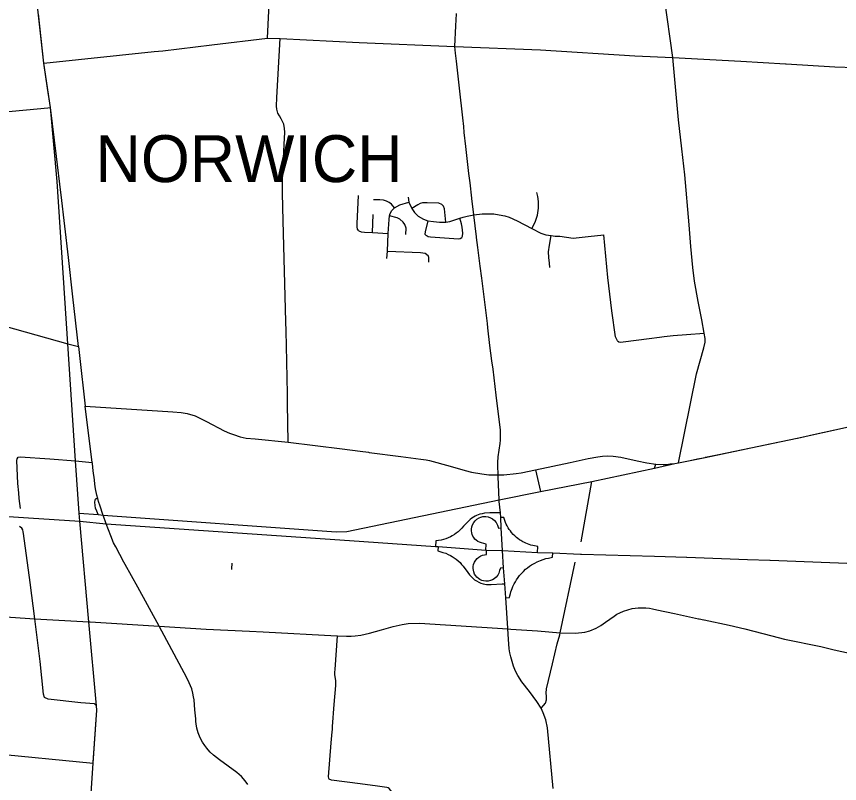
# Model space of a CAD drawing. Extents: x 1755200 to 1902939, y 644115 to 788070.
# Drawn here: x 1776912 to 1792682, y 716346 to 731049 of the extents above; entities that cross this region are included whole.
import ezdxf

# ---------------------------------------------------------------- set-up
doc = ezdxf.new("R2010")
doc.units = 0
for name, color, linetype in [('GM_X_City_Street', 7, 'Continuous'), ('GM_X_County_Road', 7, 'Continuous'), ('GM_X_Interchange_Ramps', 7, 'Continuous'), ('GM_X_Interstate_Route', 7, 'Continuous'), ('GM_X_Township', 7, 'Continuous'), ('GM_X_Township_Road', 7, 'Continuous'), ('GM_X_Township_Text', 7, 'Continuous')]:
    doc.layers.add(name, color=color, linetype=linetype)

msp = doc.modelspace()

# ---------------------------------------------------------------- linework, layer by layer
at = {"layer": 'GM_X_City_Street'}
for points in [[(1781722, 730635), (1781759, 731426)], [(1789599, 722496), (1789944, 724200), (1790081, 724699), (1790105, 724804), (1790108, 724874), (1790088, 724979), (1790041, 725234), (1789973, 725588), (1789906, 725972), (1789873, 726237), (1789834, 726638), (1789800, 727052), (1789717, 728011), (1789660, 728513), (1789596, 729067), (1789486, 730260), (1789329, 731408)], [(1777437, 730152), (1777333, 731099)], [(1785481, 728938), (1785462, 729108), (1785399, 729675), (1785340, 730193), (1785323, 730344), (1785311, 730474), (1785329, 730870), (1785343, 731097), (1785344, 731105)], [(1780654, 730505), (1781722, 730635), (1781962, 730623), (1783476, 730548), (1785311, 730474)], [(1782072, 725200), (1782025, 727132), (1782011, 727662), (1782011, 727904), (1782016, 728049), (1782039, 728595), (1782052, 728830), (1782048, 728903), (1782034, 728984), (1782010, 729034), (1781982, 729089), (1781950, 729141), (1781921, 729194), (1781903, 729270), (1781893, 729331), (1781902, 729493), (1781962, 730623)], [(1777437, 730152), (1779548, 730374)], [(1785311, 730474), (1786954, 730410), (1788762, 730295), (1789486, 730260), (1790791, 730191), (1791647, 730138), (1791657, 730138)], [(1777509, 729675), (1777437, 730152)], [(1791657, 730138), (1792592, 730086), (1793371, 730056), (1793934, 730030)], [(1785638, 727562), (1785638, 727565), (1785602, 727860), (1785582, 728036), (1785520, 728559), (1785493, 728824), (1785481, 728938)], [(1786787, 726983), (1786850, 727104), (1786896, 727243), (1786916, 727371), (1786915, 727505), (1786903, 727598), (1786882, 727676)], [(1783473, 726942), (1783447, 726974), (1783438, 727018), (1783442, 727081), (1783466, 727619)], [(1784156, 727383), (1784098, 727453), (1784050, 727485), (1784005, 727508), (1783944, 727527), (1783871, 727531), (1783814, 727533), (1783752, 727532)], [(1784417, 727588), (1784432, 727489), (1784485, 727367), (1784541, 727288), (1784607, 727223), (1784713, 727163), (1784793, 727134), (1784905, 727116), (1785020, 727109), (1785137, 727107), (1785214, 727119), (1785274, 727137), (1785407, 727185), (1785469, 727203), (1785548, 727223), (1785678, 727244), (1785835, 727263), (1785929, 727266), (1786058, 727263), (1786160, 727248), (1786268, 727226), (1786355, 727200), (1786505, 727130), (1786787, 726983), (1786961, 726898), (1787055, 726866), (1787155, 726848), (1787236, 726835), (1787325, 726835), (1787577, 726802), (1787866, 726833), (1788164, 726860)], [(1785725, 726822), (1785678, 727244), (1785638, 727562)], [(1784011, 726412), (1784018, 726553), (1784035, 726887), (1784050, 727154), (1784058, 727227), (1784073, 727275), (1784101, 727327), (1784156, 727383), (1784256, 727440), (1784432, 727489)], [(1785137, 727107), (1785111, 727360), (1785093, 727412), (1785059, 727447), (1785003, 727469), (1784778, 727479), (1784693, 727476), (1784650, 727464), (1784600, 727438), (1784485, 727367)], [(1783731, 726909), (1783748, 727253)], [(1784370, 726872), (1784377, 726993), (1784356, 727063), (1784319, 727107), (1784256, 727166), (1784209, 727188), (1784058, 727227)], [(1784793, 727134), (1784740, 726920), (1784739, 726876), (1784757, 726856), (1784779, 726841), (1784803, 726833), (1784842, 726826), (1785379, 726789), (1785416, 726794), (1785443, 726813), (1785461, 726837), (1785467, 726893), (1785451, 727009), (1785439, 727076), (1785407, 727185)], [(1783473, 726942), (1783516, 726918), (1783579, 726911), (1783731, 726909), (1784035, 726887)], [(1785944, 725080), (1785934, 725163), (1785829, 726034), (1785797, 726263), (1785749, 726618), (1785727, 726809), (1785725, 726822)], [(1787131, 726234), (1787123, 726318), (1787110, 726429), (1787108, 726536), (1787125, 726664), (1787155, 726848)], [(1788430, 724830), (1788414, 724854), (1788391, 724907), (1788322, 725405), (1788242, 726047), (1788164, 726860)], [(1784018, 726553), (1784656, 726527), (1784745, 726512), (1784800, 726470)], [(1784813, 726336), (1784815, 726427), (1784800, 726470)], [(1786023, 724447), (1785985, 724743), (1785944, 725080)], [(1788430, 724830), (1788453, 724811), (1788485, 724807), (1788535, 724810), (1789035, 724873), (1789230, 724902), (1789322, 724916), (1789493, 724935), (1789747, 724953), (1790088, 724979)], [(1786177, 722862), (1786186, 722926), (1786188, 722992), (1786185, 723126), (1786167, 723272), (1786100, 723790), (1786043, 724289), (1786023, 724447)], [(1782118, 722891), (1782108, 723626)], [(1792243, 723049), (1793294, 723280)], [(1791139, 722812), (1791871, 722968), (1791876, 722969)], [(1786144, 722227), (1786143, 722261), (1786134, 722441), (1786134, 722500), (1786139, 722606), (1786159, 722733), (1786177, 722862)], [(1790369, 722653), (1791139, 722812)], [(1783669, 722693), (1784274, 722615), (1784658, 722566), (1784761, 722550), (1784824, 722538), (1785222, 722427), (1785506, 722345), (1785630, 722316), (1785830, 722280), (1785960, 722266), (1786035, 722260), (1786143, 722261)], [(1786143, 722261), (1786248, 722260), (1786485, 722288), (1786583, 722303), (1786857, 722360), (1787188, 722430), (1787520, 722499), (1787864, 722574), (1788050, 722609), (1788142, 722622), (1788238, 722626), (1788343, 722621), (1788491, 722603), (1788802, 722533), (1788989, 722493), (1789163, 722468), (1789300, 722462), (1789367, 722464), (1789438, 722471), (1789524, 722482), (1789599, 722496)], [(1790113, 722599), (1790369, 722653)], [(1786857, 722360), (1786950, 721943), (1787934, 722138), (1789139, 722388), (1789163, 722468)], [(1789599, 722496), (1789790, 722531), (1789959, 722567)], [(1786163, 721749), (1786160, 721782), (1786144, 722227)], [(1787733, 720981), (1787934, 722138)], [(1786226, 720812), (1786201, 721246), (1786190, 721444), (1786184, 721537), (1786163, 721749)], [(1786327, 719326), (1786290, 719906), (1786268, 720174), (1786246, 720478), (1786226, 720812)], [(1787320, 719199), (1787329, 719236), (1787619, 720589)], [(1781038, 720449), (1781038, 720459), (1781044, 720567)], [(1786381, 719305), (1786895, 719271), (1787329, 719236), (1787624, 719226), (1787799, 719248), (1787899, 719274), (1788018, 719323), (1788109, 719374), (1788197, 719440), (1788282, 719499), (1788362, 719557), (1788417, 719590), (1788470, 719618), (1788546, 719649), (1788624, 719678), (1788707, 719700), (1788824, 719713), (1788924, 719715), (1788968, 719713), (1789040, 719705), (1789096, 719694), (1789183, 719676), (1789523, 719603), (1789981, 719504)], [(1790085, 719484), (1790089, 719483), (1790569, 719379), (1790869, 719309), (1791383, 719177), (1791627, 719116), (1792323, 718971), (1792577, 718912), (1792962, 718825)], [(1783263, 719169), (1783325, 719170), (1783403, 719178), (1783511, 719193), (1783677, 719231), (1783905, 719292), (1784132, 719358), (1784299, 719394), (1784417, 719415), (1784631, 719419), (1786328, 719309)], [(1786368, 718852), (1786355, 718926), (1786340, 719112), (1786328, 719309), (1786327, 719326)], [(1786328, 719309), (1786381, 719305)], [(1781637, 719255), (1783053, 719176)], [(1782968, 717441), (1782998, 717861), (1783028, 718226), (1783031, 718323), (1783015, 718429), (1783014, 718484), (1783018, 718530), (1783066, 719175)], [(1783053, 719176), (1783066, 719175), (1783237, 719168), (1783263, 719169)], [(1781345, 716326), (1781294, 716396), (1781222, 716481), (1781131, 716559), (1780799, 716801), (1780688, 716890), (1780624, 716945), (1780585, 716989), (1780557, 717023), (1780518, 717077), (1780476, 717141), (1780433, 717222), (1780393, 717317), (1780368, 717406), (1780353, 717490), (1780348, 717537), (1780346, 717584), (1780340, 717647)], [(1782943, 717125), (1782960, 717335)], [(1784287, 711268), (1784257, 712144), (1784154, 713990), (1784169, 714040), (1784177, 714106), (1784191, 714939), (1784196, 715048), (1784189, 715097), (1784160, 715152), (1784098, 715241), (1784082, 715270), (1784077, 715304), (1784083, 715438), (1784109, 715887), (1784118, 716104), (1784106, 716186), (1784052, 716249), (1784033, 716263), (1784011, 716269), (1783831, 716296), (1783496, 716342), (1782951, 716412), (1782905, 716430), (1782898, 716443)]]:
    msp.add_lwpolyline(points, dxfattribs=at)
at = {"layer": 'GM_X_County_Road'}
for points in [[(1779548, 730374), (1779718, 730392), (1780654, 730505)], [(1777565, 729305), (1777509, 729675)], [(1771794, 729168), (1772912, 729117), (1773134, 729105), (1773270, 729095), (1773412, 729078), (1773515, 729060), (1773633, 729037), (1773733, 729018), (1773839, 729000), (1773954, 728991), (1774076, 728987), (1774241, 728991), (1774436, 729008), (1777513, 729300)], [(1777513, 729300), (1777565, 729305)], [(1777761, 727673), (1777676, 728365), (1777565, 729305)], [(1778102, 724724), (1777991, 725673), (1777906, 726429), (1777766, 727631), (1777761, 727673)], [(1774090, 726031), (1775440, 725510), (1775595, 725449), (1775701, 725407), (1775843, 725352), (1777898, 724773), (1778050, 724736)], [(1782108, 723626), (1782105, 723813), (1782086, 724734), (1782077, 725019), (1782072, 725200)], [(1778050, 724736), (1778102, 724724)], [(1778102, 724724), (1778102, 724724), (1778122, 724551), (1778230, 723582)], [(1778230, 723582), (1779906, 723471), (1780068, 723459), (1780184, 723441), (1780336, 723397), (1780556, 723288), (1780893, 723105), (1780991, 723062), (1781071, 723035), (1781200, 722994), (1781312, 722967), (1781488, 722953), (1782118, 722891), (1783151, 722760), (1783499, 722716), (1783658, 722695), (1783669, 722693)], [(1778366, 722482), (1778364, 722500), (1778230, 723582)], [(1791876, 722969), (1792243, 723049)], [(1778567, 721503), (1778513, 721662), (1778485, 721753), (1778471, 721807), (1778452, 721875), (1778429, 721994), (1778416, 722082), (1778407, 722166), (1778383, 722339), (1778366, 722482)], [(1789959, 722567), (1790107, 722598), (1790113, 722599)], [(1778997, 720542), (1778970, 720591), (1778814, 720882), (1778774, 720958), (1778717, 721095), (1778630, 721327), (1778572, 721489), (1778567, 721503)], [(1780340, 717647), (1780330, 717759), (1780314, 717949), (1780306, 718007), (1780291, 718077), (1780271, 718161), (1780221, 718274), (1780174, 718372), (1779645, 719365), (1779236, 720110), (1778997, 720542)], [(1774468, 719669), (1774852, 719655), (1775486, 719628), (1776050, 719595), (1776800, 719535), (1777265, 719506)], [(1777265, 719506), (1778300, 719446), (1778323, 719445)], [(1778383, 716752), (1778451, 717750), (1778446, 717837), (1778405, 717872), (1778148, 717895), (1777521, 717965), (1777448, 717994), (1777431, 718062), (1777369, 718687), (1777265, 719506)], [(1789981, 719504), (1789991, 719502), (1790085, 719484)], [(1778323, 719445), (1779645, 719365)], [(1779645, 719365), (1780547, 719307), (1781379, 719269), (1781637, 719255)], [(1786377, 718800), (1786368, 718852)], [(1787195, 716249), (1787089, 717411), (1787053, 717569), (1787002, 717704), (1786965, 717790), (1786881, 717920), (1786742, 718112), (1786597, 718293), (1786518, 718417), (1786476, 718502), (1786436, 718596), (1786382, 718773), (1786377, 718800)], [(1778328, 710978), (1778377, 712260), (1778410, 712855), (1778426, 713251), (1778403, 713518), (1778357, 713873), (1778305, 714235), (1778267, 714578), (1778265, 714786), (1778304, 715585), (1778382, 716739), (1778383, 716752)]]:
    msp.add_lwpolyline(points, dxfattribs=at)
at = {"layer": 'GM_X_Interchange_Ramps'}
for points in [[(1786184, 721537), (1786129, 721533), (1785985, 721536), (1785879, 721526), (1785837, 721517), (1785792, 721506), (1785760, 721496), (1785728, 721483), (1785699, 721469), (1785670, 721453), (1785637, 721431), (1785608, 721409), (1785581, 721384), (1785555, 721357), (1785478, 721279), (1785446, 721241), (1785416, 721210), (1785373, 721172), (1785337, 721143), (1785302, 721119), (1785263, 721095), (1785225, 721075), (1785184, 721056), (1785139, 721039), (1785097, 721025), (1785047, 721013), (1784948, 720996), (1784941, 720889)], [(1785902, 720820), (1785910, 720934), (1785820, 720958), (1785783, 720971), (1785754, 720986), (1785723, 721008), (1785697, 721033), (1785675, 721060), (1785659, 721088), (1785645, 721119), (1785636, 721151), (1785630, 721188), (1785630, 721224), (1785636, 721265), (1785650, 721307), (1785673, 721349), (1785698, 721382), (1785735, 721414), (1785777, 721440), (1785810, 721452), (1785850, 721462), (1785902, 721464), (1785949, 721457), (1785994, 721441), (1786034, 721418), (1786070, 721389), (1786101, 721350), (1786127, 721300), (1786146, 721242), (1786201, 721246)], [(1786895, 720777), (1786899, 720892), (1786808, 720909), (1786770, 720918), (1786738, 720928), (1786703, 720940), (1786670, 720953), (1786645, 720965), (1786611, 720982), (1786577, 721002), (1786549, 721020), (1786517, 721043), (1786490, 721065), (1786458, 721093), (1786430, 721121), (1786399, 721156), (1786375, 721187), (1786353, 721217), (1786334, 721247), (1786312, 721286), (1786295, 721320), (1786282, 721350), (1786268, 721388), (1786248, 721448), (1786190, 721444)], [(1784989, 720887), (1784983, 720804), (1785082, 720777), (1785136, 720759), (1785184, 720738), (1785225, 720718), (1785263, 720696), (1785299, 720673), (1785334, 720647), (1785372, 720617), (1785411, 720580), (1785442, 720547), (1785472, 720512), (1785561, 720392), (1785592, 720348), (1785623, 720313), (1785658, 720280), (1785691, 720253), (1785727, 720229), (1785768, 720207), (1785812, 720188), (1785851, 720176), (1785887, 720167), (1785921, 720161), (1785966, 720158), (1786009, 720158), (1786218, 720171), (1786268, 720174)], [(1786246, 720478), (1786185, 720476), (1786169, 720427), (1786155, 720380), (1786133, 720339), (1786100, 720299), (1786066, 720270), (1786031, 720249), (1785996, 720235), (1785951, 720226), (1785904, 720224), (1785862, 720230), (1785829, 720240), (1785793, 720257), (1785764, 720275), (1785734, 720302), (1785711, 720329), (1785691, 720362), (1785675, 720401), (1785667, 720433), (1785663, 720467), (1785664, 720504), (1785672, 720547), (1785687, 720589), (1785711, 720630), (1785737, 720660), (1785770, 720688), (1785811, 720712), (1785843, 720724), (1785877, 720732), (1785915, 720736), (1785921, 720819)], [(1786290, 719906), (1786357, 719909), (1786365, 719947), (1786376, 719988), (1786385, 720020), (1786397, 720055), (1786409, 720087), (1786424, 720121), (1786448, 720172), (1786471, 720213), (1786493, 720250), (1786523, 720293), (1786553, 720333), (1786588, 720374), (1786626, 720413), (1786668, 720452), (1786702, 720481), (1786742, 720511), (1786783, 720538), (1786841, 720573), (1786890, 720598), (1786950, 720623), (1787006, 720643), (1787057, 720658), (1787103, 720669), (1787183, 720684), (1787186, 720768)]]:
    msp.add_lwpolyline(points, dxfattribs=at)
at = {"layer": 'GM_X_Interstate_Route'}
for points in [[(1776556, 721476), (1776858, 721457), (1777140, 721440)], [(1777140, 721440), (1778124, 721378), (1778630, 721327), (1783296, 721004)], [(1783296, 721004), (1784941, 720889), (1784989, 720887), (1785902, 720820), (1785921, 720819), (1786208, 720813)], [(1786208, 720813), (1786226, 720812), (1786895, 720777), (1787186, 720768), (1787719, 720741)], [(1787719, 720741), (1787738, 720740), (1789136, 720705), (1789747, 720684)], [(1789747, 720684), (1789758, 720683), (1790917, 720643), (1791348, 720629)], [(1791348, 720629), (1791353, 720629), (1793642, 720537), (1793692, 720535), (1794324, 720509), (1794373, 720507), (1795006, 720482)]]:
    msp.add_lwpolyline(points, dxfattribs=at)
at = {"layer": 'GM_X_Township'}
for points in [[(1778112, 721526), (1778045, 722532), (1777898, 724773), (1777691, 727884), (1777565, 729305), (1777437, 730152), (1776883, 735163)], [(1776417, 716930), (1778382, 716739), (1778451, 717750), (1778446, 717837), (1778300, 719446), (1778124, 721378), (1778112, 721526), (1778478, 721503), (1778572, 721489), (1783037, 721173), (1783239, 721176), (1786160, 721782), (1786950, 721943), (1787934, 722138), (1789139, 722388), (1789524, 722482), (1789599, 722496), (1789790, 722531), (1790107, 722598), (1791228, 722831), (1791871, 722968), (1793347, 723291)]]:
    msp.add_lwpolyline(points, dxfattribs=at)
at = {"layer": 'GM_X_Township_Road'}
for points in [[(1776987, 721618), (1776965, 721810), (1776958, 721917), (1776941, 722099), (1776926, 722392), (1776917, 722538), (1776922, 722567), (1776944, 722600), (1776985, 722610), (1777553, 722568)], [(1777553, 722568), (1778045, 722532), (1778364, 722500)], [(1778478, 721503), (1778449, 721564), (1778428, 721624), (1778421, 721673), (1778415, 721739), (1778418, 721779), (1778426, 721796), (1778442, 721808), (1778471, 721807)], [(1777047, 721137), (1777043, 721168), (1777033, 721210), (1777012, 721238), (1776973, 721270)], [(1777265, 719506), (1777176, 720198), (1777047, 721137)], [(1787065, 718019), (1787063, 718078), (1787069, 718163), (1787181, 718640), (1787275, 719025), (1787320, 719199)], [(1786965, 717790), (1787013, 717839), (1787048, 717887), (1787066, 717948), (1787065, 718005), (1787065, 718019)], [(1782960, 717335), (1782964, 717385), (1782968, 717441)], [(1782898, 716443), (1782894, 716450), (1782892, 716473), (1782943, 717125)]]:
    msp.add_lwpolyline(points, dxfattribs=at)

# ---------------------------------------------------------------- texts
at = {"layer": 'GM_X_Township_Text'}
msp.add_text('NORWICH', height=900, rotation=0, dxfattribs=at).set_placement((1778427, 727873))

doc.saveas('drawing.dxf')
